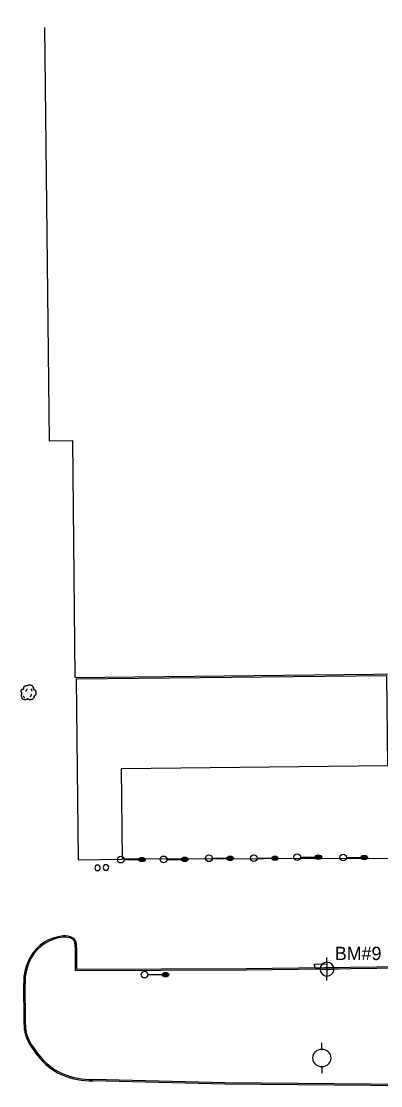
# Model space of a CAD drawing. Extents: x 2145380 to 2156929, y 139568 to 149130.
# Drawn here: x 2147862.8 to 2148024.6, y 143189.7 to 143668.4 of the extents above; entities that cross this region are included whole.
import ezdxf

# ---------------------------------------------------------------- set-up
doc = ezdxf.new("R2010")
doc.units = 0
for name, color, linetype in [('SURV_Benchmark', 7, 'Continuous'), ('SURV_Text', 7, 'Continuous'), ('TOPO_Building', 7, 'Continuous'), ('TOPO_Curb Back', 7, 'Continuous'), ('TOPO_DRAIN_Inlet Grate', 7, 'Continuous'), ('TOPO_Fence', 7, 'Continuous'), ('TOPO_Light Pole', 7, 'Continuous'), ('TOPO_Misc', 7, 'Continuous'), ('TOPO_Misc Line', 7, 'Continuous'), ('TOPO_Power Pole', 7, 'Continuous'), ('TOPO_Tree', 7, 'Continuous')]:
    doc.layers.add(name, color=color, linetype=linetype)

# ---------------------------------------------------------------- blocks, each defined once
blk = doc.blocks.new('POST')
at = {"layer": 'TOPO_Misc'}
for start, end in [(90, 180), (180, 270), (360, 90), (270, 0)]:
    blk.add_arc((0, 0), 3.16, start, end, dxfattribs=at)
blk = doc.blocks.new('LP')
at = {"layer": 'TOPO_Light Pole'}
blk.add_line((3.8, 0), (20.3, 0), dxfattribs=at)
for points in [[(20.3, 0), (27.9, 0)], [(20.3, 0), (23.5, 0)], [(20.8, 1.3), (27.4, 1.3)], [(20.8, 1.3), (23.5, 1.3)], [(23.7, 1.3), (27.4, 1.3)], [(23.7, 0), (27.9, 0)], [(20.8, -1.3), (27.4, -1.3)], [(20.8, -1.3), (23.5, -1.3)], [(23.7, -1.3), (27.4, -1.3)]]:
    blk.add_lwpolyline(points, dxfattribs=at)
blk.add_circle((0, 0), 3.81, dxfattribs=at)
blk.add_ellipse((24.1, 0), major_axis=(3.81, 0), ratio=0.666667, dxfattribs=at)
blk = doc.blocks.new('TREE')
at = {"layer": 'TOPO_Tree'}
for points in [[(-14.1, -0.4), (-14.2, 0.5), (-14.4, 1.4), (-14.6, 2.3), (-14.8, 3.2), (-15.5, 4), (-15.7, 4.9), (-15.8, 5.6), (-15.7, 6.3), (-15.7, 7), (-15.6, 7.9), (-15.7, 8.8), (-15.1, 9.7), (-14.6, 10.4), (-13.8, 10.5), (-13, 10.7), (-12.2, 11), (-11.1, 10), (-10.4, 10.7), (-9.4, 11.7), (-10.3, 13.3), (-9.8, 14.4), (-9.6, 15.1), (-9.3, 15.9), (-8.8, 16.5), (-8.2, 17.3), (-7.5, 17.7), (-6.7, 18.1), (-6.1, 18.4), (-5.6, 18.6), (-5.1, 18.7), (-4.5, 18.7), (-4, 18.5), (-3.5, 18.1)], [(13.2, -5.3), (13.3, -5.8), (13.4, -6.3), (13.4, -6.7), (13.8, -8.5), (12.2, -10), (10.8, -11.5), (10, -12.3), (9.1, -12.8), (8.2, -13.1), (6, -13.8), (3.3, -13.6), (1.3, -13.1), (0.5, -12.9), (-0.1, -11.4), (-0.8, -11.5), (-2, -11.6), (-3.3, -12.8), (-4.5, -13.1), (-6.1, -13.5), (-7.8, -14), (-9.3, -13.6), (-11.4, -13.1), (-12.8, -11.4), (-14.1, -9.4), (-15.3, -7.3), (-15.6, -5.1), (-15.1, -3), (-14.9, -1.9), (-13.9, -0.8), (-13.5, 0.1)], [(-4.2, 5.1), (-4.5, 6.1), (-4.3, 7.2), (-3.8, 8.2), (-3.3, 9.3), (-2.7, 10.3), (-1.6, 11)], [(-3.5, 17.6), (-3.1, 18.3), (-2.6, 18.8), (-1.9, 19.2), (-1, 19.7), (-0.2, 20), (0.7, 20.2), (1.6, 20.5), (2.5, 20.8), (3.4, 20.8), (4.1, 20.7), (4.8, 20.5), (5.5, 20.2), (6.4, 19.9), (7.3, 19.7), (8.2, 19.2), (9.4, 18.4), (10, 17.2), (10.8, 16), (11.2, 15.3), (11.6, 14.6), (11.9, 13.9), (12.2, 13.1), (11.4, 12), (11.9, 11.2), (12, 11), (12.2, 10.9), (12.4, 10.7), (12.9, 10.4), (13.5, 10), (14, 9.7), (14.7, 9.2), (15.4, 8.7), (16.1, 8.1), (16.7, 7.5), (16.9, 6.7), (17.1, 6), (17.6, 4.4), (17.7, 2.8), (17.7, 1.2), (17.7, -0.2), (17.8, -2.2), (16.6, -3), (15.5, -3.8), (14.3, -4.6), (13.2, -5.3)], [(5.9, 11.2), (6.5, 10.7), (7, 10.2), (7.4, 9.5), (7.9, 8.6), (8.3, 7.6), (8.5, 6.6)], [(-11.4, -4.5), (-11.5, -5.4), (-11, -6.3), (-10.1, -7.2), (-9.3, -8), (-8.5, -8.3), (-7.7, -8.1)], [(4.8, -6.3), (5.7, -5.7), (6.3, -4.9), (6.8, -3.9), (7.4, -2.8), (7.6, -1.7), (7.5, -0.6)]]:
    blk.add_open_spline(points, degree=3, dxfattribs=at)
blk = doc.blocks.new('POWPOL')
at = {"layer": 'TOPO_Power Pole'}
for p, q in [((0, 10.2), (0, 17.3)), ((0, -10.2), (0, -17.3))]:
    blk.add_line(p, q, dxfattribs=at)
blk.add_circle((0, 0), 10.2, dxfattribs=at)
blk = doc.blocks.new('BM')
at = {"layer": 'SURV_Benchmark'}
for p, q in [((0, 2.49), (0, 4.15)), ((-2.49, 0), (-4.16, 0)), ((4.16, 0), (2.49, 0)), ((0, -4.16), (0, -2.49))]:
    blk.add_line(p, q, dxfattribs=at)
for points in [[(-2.5, 0), (-2.49, 0), (0, 0), (0, -2.49), (0, -2.49)], [(-2.5, 0), (-2.49, 0), (0, 0), (0, -2.49), (0, -2.49)], [(0, 2.49), (0, 2.49), (0, 0), (2.49, 0), (2.49, 0), (2.49, 0)], [(0, 2.49), (0, 2.49), (0, 0), (2.49, 0), (2.49, 0), (2.49, 0), (2.49, 0)]]:
    blk.add_lwpolyline(points, dxfattribs=at)
for start, end in [(90.0638, 180.0068), (0.0638, 90.0068), (0.0638, 90.0068), (180.0638, 270.0068), (180.0638, 270.0068), (269.9472, 359.9927)]:
    blk.add_arc((0, 0), 2.5, start, end, dxfattribs=at)

msp = doc.modelspace()

# ---------------------------------------------------------------- linework, layer by layer
at = {"layer": 'TOPO_Building'}
msp.add_lwpolyline([(2147873.27, 143665.68), (2147875.33, 143479.79), (2147885.79, 143479.91), (2147886.96, 143373.39), (2148061.61, 143375.32), (2148062.53, 143291.91), (2148110.45, 143292.43), (2148108.62, 143458.32), (2148117.66, 143458.42), (2148117.71, 143453.92), (2148177.01, 143454.58), (2148176.97, 143458.5), (2148180.6, 143458.54), (2148178.28, 143668.45)], dxfattribs=at)
at = {"layer": 'TOPO_Curb Back'}
for points in [[(2147886.94, 143253.61), (2147887, 143250.5), (2147887.04, 143241.54), (2147964.05, 143241.93), (2148046.3, 143242.85), (2148081.65, 143243.66), (2148090.34, 143244.19)], [(2147887.54, 143253.61), (2147887.6, 143250.51), (2147887.64, 143242.14), (2147964.04, 143242.53), (2148046.29, 143243.45), (2148081.62, 143244.26), (2148090.27, 143244.79)], [(2147864.07, 143218.62), (2147863.88, 143235.7)], [(2147864.67, 143218.65), (2147864.48, 143235.72)], [(2148215.03, 143191.07), (2148189.03, 143190.98), (2148104.77, 143190.12), (2148036.43, 143189.75), (2147954.44, 143190.43), (2147894.97, 143191.9)], [(2148215.03, 143191.67), (2148189.03, 143191.58), (2148104.76, 143190.72), (2148036.43, 143190.35), (2147954.45, 143191.03), (2147894.98, 143192.5)]]:
    msp.add_lwpolyline(points, dxfattribs=at)
for centre, radius, start, end in [((2147883.15, 143238.45), 18.7, 94.5975, 150.2856), ((2147883.15, 143238.45), 18.1, 94.5477, 150.289), ((2147882.56, 143250.21), 6.95, 61.1162, 97.5467), ((2147882.56, 143250.21), 6.35, 61.0318, 97.6848), ((2147884.55, 143253.64), 2.99, 359.4962, 62.8417), ((2147884.55, 143253.64), 2.39, 359.2981, 63.0472), ((2147886.65, 143236.37), 22.78, 150.1012, 181.6745), ((2147886.65, 143236.37), 22.18, 150.0988, 181.6883), ((2147819.7, 143214.93), 44.52, 359.8523, 4.7525), ((2147819.74, 143214.93), 45.08, 359.9052, 4.726), ((2147881.3, 143217.25), 17.24, 188.1278, 220.4372), ((2147881.3, 143217.25), 16.64, 188.2752, 220.6009), ((2147893.23, 143221.33), 29.34, 211.3489, 246.3178), ((2147893.23, 143221.33), 28.74, 211.2534, 246.2976), ((2147894.83, 143228.07), 36.17, 248.2817, 270.2294), ((2147894.83, 143228.07), 35.57, 248.2987, 270.2423)]:
    msp.add_arc(centre, radius, start, end, dxfattribs=at)
at = {"layer": 'TOPO_DRAIN_Inlet Grate'}
msp.add_lwpolyline([(2147994.99, 143242.88), (2147994.67, 143244.39), (2148000.25, 143244.63), (2148000.27, 143242.94)], dxfattribs=at)
at = {"layer": 'TOPO_Fence'}
msp.add_line((2148062.53, 143291.91), (2147908.35, 143291.61), dxfattribs=at)
at = {"layer": 'TOPO_Misc Line'}
msp.add_lwpolyline([(2148027.34, 143374.15), (2147887.53, 143372.57), (2147888.45, 143291.38), (2147908.35, 143291.61), (2147907.89, 143332.41), (2148027.8, 143333.76)], close=True, dxfattribs=at)

# ---------------------------------------------------------------- block references
at = {"layer": 'SURV_Benchmark', "xscale": 1.25, "yscale": 1.25}
msp.add_blockref('BM', (2148000.37, 143242.2), dxfattribs=at)
at = {"layer": 'TOPO_Light Pole', "xscale": 0.39370000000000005, "yscale": 0.3937000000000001}
for p in [(2147907.61, 143291.43), (2147926.85, 143291.55), (2147947.27, 143292.02), (2147967.45, 143292.04), (2147986.99, 143292.55), (2148007.65, 143292.39), (2147918.22, 143239.7)]:
    msp.add_blockref('LP', p, dxfattribs=at)
at = {"layer": 'TOPO_Misc', "xscale": 0.39370000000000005, "yscale": 0.3937000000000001}
for p in [(2147897.12, 143287.72), (2147900.88, 143287.9)]:
    msp.add_blockref('POST', p, dxfattribs=at)
at = {"layer": 'TOPO_Power Pole', "xscale": 0.39370000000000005, "yscale": 0.3937000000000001}
msp.add_blockref('POWPOL', (2147998.05, 143202.21), dxfattribs=at)
at = {"layer": 'TOPO_Tree', "xscale": 0.19685000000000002, "yscale": 0.19685000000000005}
msp.add_blockref('TREE', (2147865.89, 143366), dxfattribs=at)

# ---------------------------------------------------------------- texts
at = {"layer": 'SURV_Text'}
msp.add_text('BM#9', height=6, dxfattribs=at).set_placement((2148003.93, 143246.25))

doc.saveas('drawing.dxf')
